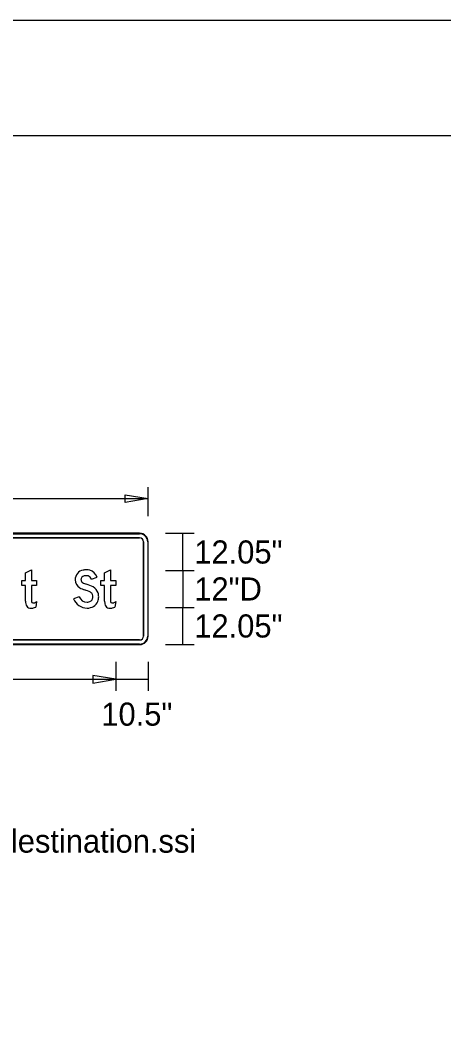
# Model space of a CAD drawing. Extents: x 1806251 to 1809821, y 414895 to 422886.
# Drawn here: x 1809677.959 to 1809679.337, y 415000.976 to 415004.226 of the extents above; entities that cross this region are included whole.
import ezdxf

# ---------------------------------------------------------------- set-up
doc = ezdxf.new("R2010")
doc.units = 0
for name, color, linetype in [('GSBWFILL', 7, 'Continuous'), ('GSCOLORFILL', 7, 'Continuous'), ('GSDIMS', 7, 'Continuous'), ('GSOUTLINE', 7, 'Continuous'), ('GSSHT', 7, 'Continuous')]:
    doc.layers.add(name, color=color, linetype=linetype)

msp = doc.modelspace()

# ---------------------------------------------------------------- linework, layer by layer
at = {"layer": 'GSBWFILL'}
for p, q in [((1809678.3481, 415002.5611), (1809676.8421, 415002.5611)), ((1809676.8421, 415002.5461), (1809678.3481, 415002.5461)), ((1809678.3606, 415002.5336), (1809678.3606, 415002.2276)), ((1809678.3756, 415002.2276), (1809678.3756, 415002.5336)), ((1809678.0134, 415002.3398), (1809678.0108, 415002.322)), ((1809678.2702, 415002.3398), (1809678.2676, 415002.322)), ((1809678.3481, 415002.2151), (1809676.8422, 415002.2151)), ((1809676.8422, 415002.2001), (1809678.3481, 415002.2001))]:
    msp.add_line(p, q, dxfattribs=at)
for points in [[(1809677.9774, 415002.341), (1809677.9774, 415002.3914), (1809677.9654, 415002.3914), (1809677.9654, 415002.4082), (1809677.9774, 415002.4082), (1809677.9774, 415002.4331), (1809677.9966, 415002.4427), (1809677.9966, 415002.4082), (1809678.0134, 415002.4082), (1809678.0134, 415002.3914), (1809677.9966, 415002.3914), (1809677.9966, 415002.344)], [(1809678.1916, 415002.4123), (1809678.2098, 415002.4184)], [(1809678.2342, 415002.341), (1809678.2342, 415002.3914), (1809678.2222, 415002.3914), (1809678.2222, 415002.4082), (1809678.2342, 415002.4082), (1809678.2342, 415002.4331), (1809678.2534, 415002.4427), (1809678.2534, 415002.4082), (1809678.2702, 415002.4082), (1809678.2702, 415002.3914), (1809678.2534, 415002.3914), (1809678.2534, 415002.344)], [(1809678.1514, 415002.3555), (1809678.1334, 415002.3487)]]:
    msp.add_lwpolyline(points, dxfattribs=at)
for centre, radius, start, end in [((1809678.3481, 415002.5336), 0.0275, 0, 90), ((1809678.3481, 415002.5336), 0.0125, 0, 90), ((1809678.3481, 415002.2276), 0.0275, 270, 0), ((1809678.3481, 415002.2276), 0.0125, 270, 0)]:
    msp.add_arc(centre, radius, start, end, dxfattribs=at)
for centre, major_axis, ratio, start_param, end_param in [((1809678.1703, 415002.4103), (0, 0.032), 0.999999, 0.175685, 1.570796), ((1809678.1703, 415002.4103), (0, 0.0128), 0.999999, 0.175685, 1.570796), ((1809678.1739, 415002.3905), (0, 0.0521), 0.999999, 0.090794, 0.175685), ((1809678.1739, 415002.3905), (0, 0.0329), 0.999999, 0.090794, 0.175685), ((1809678.1755, 415002.3729), (0, 0.0698), 0.999999, 6.283185, 6.373979), ((1809678.1755, 415002.3729), (0, 0.0506), 0.999999, 0, 0.090794), ((1809678.1755, 415002.4045), (0, 0.0382), 0.999999, 6.012094, 6.283185), ((1809678.1755, 415002.4045), (0, 0.019), 0.999999, 6.012094, 6.283185), ((1809678.1762, 415002.4072), (0, 0.0162), 0.999999, 5.034126, 6.012094), ((1809678.1762, 415002.4072), (0, 0.0354), 0.999999, 5.034126, 6.012094), ((1809678.168, 415002.4103), (0, 0.0296), 0.999999, 1.570796, 2.627164), ((1809678.168, 415002.4103), (0, 0.0104), 0.999999, 1.570796, 2.627164), ((1809678.1951, 415002.4583), (0, 0.0655), 0.999999, 2.627164, 2.834816), ((1809678.1303, 415002.2539), (0, 0.149), 0.999999, 5.820582, 5.976409), ((1809678.1825, 415002.3585), (0, 0.032), 0.999999, 5.010707, 5.820582), ((1809678.1771, 415002.3652), (0, 0.0275), 0.999999, 1.931277, 3.141593), ((1809678.1951, 415002.4583), (0, 0.0847), 0.999999, 2.627164, 2.834816), ((1809678.1303, 415002.2539), (0, 0.1298), 0.999999, 5.820582, 5.976409), ((1809678.1825, 415002.3585), (0, 0.0128), 0.999999, 5.010707, 5.820582), ((1809678.1753, 415002.3552), (0, 0.0205), 0.999999, 4.331279, 4.712389), ((1809678.1716, 415002.3552), (0, 0.0242), 0.999999, 4.712389, 5.010707), ((1809678.1753, 415002.3552), (0, 0.0397), 0.999999, 4.331279, 4.712389), ((1809678.1716, 415002.3552), (0, 0.0434), 0.999999, 4.712389, 5.010707), ((1809678.0284, 415002.341), (0, 0.051), 0.999998, 1.570796, 1.662322), ((1809678.0078, 415002.3389), (0, 0.0303), 0.999998, 1.653079, 1.937165), ((1809677.9948, 415002.3338), (0, 0.0164), 0.999998, 1.936133, 2.408497), ((1809677.9932, 415002.3327), (0, 0.0144), 0.999998, 2.436385, 2.996739), ((1809678.0296, 415002.344), (0, 0.033), 0.999998, 1.570796, 1.695783), ((1809678.0016, 415002.3405), (0, 0.0048), 0.999998, 1.695783, 2.93591), ((1809678.0031, 415002.3474), (0, 0.0119), 0.999998, 2.93591, 3.141593), ((1809678.0031, 415002.3527), (0, 0.0171), 0.999998, 3.141593, 3.322139), ((1809677.9889, 415002.3683), (0, 0.0512), 0.999998, 3.420942, 3.583276), ((1809678.0045, 415002.3447), (0, 0.009), 0.999998, 3.322139, 3.602705), ((1809677.9972, 415002.3594), (0, 0.0254), 0.999998, 3.602705, 3.831871), ((1809678.1771, 415002.3652), (0, 0.0467), 0.999999, 1.931277, 3.141593), ((1809678.1771, 415002.3602), (0, 0.0225), 0.999999, 3.141593, 3.672524), ((1809678.1771, 415002.3602), (0, 0.0417), 0.999999, 3.141593, 3.672524), ((1809678.1815, 415002.3527), (0, 0.0139), 0.999999, 3.672524, 4.331279), ((1809678.1815, 415002.3527), (0, 0.0331), 0.999999, 3.672524, 4.331279), ((1809678.2852, 415002.341), (0, 0.051), 0.999996, 1.570796, 1.662322), ((1809678.2646, 415002.3389), (0, 0.0303), 0.999996, 1.653079, 1.937165), ((1809678.2516, 415002.3338), (0, 0.0164), 0.999996, 1.936133, 2.408497), ((1809678.25, 415002.3327), (0, 0.0144), 0.999996, 2.436385, 2.996739), ((1809678.2864, 415002.344), (0, 0.033), 0.999996, 1.570796, 1.695783), ((1809678.2584, 415002.3405), (0, 0.0048), 0.999996, 1.695783, 2.93591), ((1809678.2599, 415002.3474), (0, 0.0119), 0.999996, 2.93591, 3.141593), ((1809678.2599, 415002.3527), (0, 0.0171), 0.999996, 3.141593, 3.322139), ((1809678.2457, 415002.3683), (0, 0.0512), 0.999996, 3.420942, 3.583276), ((1809678.2613, 415002.3447), (0, 0.009), 0.999996, 3.322139, 3.602705), ((1809678.254, 415002.3594), (0, 0.0254), 0.999996, 3.602705, 3.831871), ((1809677.996, 415002.3736), (0, 0.0554), 0.999998, 3.052778, 3.141593), ((1809677.996, 415002.3507), (0, 0.0325), 0.999998, 3.141593, 3.24959), ((1809677.9973, 415002.3392), (0, 0.021), 0.999998, 3.24959, 3.420941), ((1809678.2528, 415002.3736), (0, 0.0554), 0.999996, 3.052778, 3.141593), ((1809678.2528, 415002.3507), (0, 0.0325), 0.999996, 3.141593, 3.24959), ((1809678.2541, 415002.3392), (0, 0.021), 0.999996, 3.24959, 3.420941)]:
    msp.add_ellipse(centre, major_axis=major_axis, ratio=ratio, start_param=start_param, end_param=end_param, dxfattribs=at)
at = {"layer": 'GSCOLORFILL'}
for p, q in [((1809678.3481, 415002.5611), (1809676.8421, 415002.5611)), ((1809678.3481, 415002.5611), (1809676.8421, 415002.5611)), ((1809678.3481, 415002.5611), (1809676.8421, 415002.5611)), ((1809676.8421, 415002.5596), (1809678.3481, 415002.5596)), ((1809676.8421, 415002.5461), (1809678.3481, 415002.5461)), ((1809678.3606, 415002.5336), (1809678.3606, 415002.2276)), ((1809678.3741, 415002.5336), (1809678.3741, 415002.2276)), ((1809678.3756, 415002.2276), (1809678.3756, 415002.5336)), ((1809678.3756, 415002.2276), (1809678.3756, 415002.5336)), ((1809678.3756, 415002.2276), (1809678.3756, 415002.5336)), ((1809678.0134, 415002.3398), (1809678.0108, 415002.322)), ((1809678.2702, 415002.3398), (1809678.2676, 415002.322)), ((1809678.3481, 415002.2016), (1809676.8421, 415002.2016)), ((1809676.8421, 415002.2001), (1809678.3481, 415002.2001)), ((1809676.8421, 415002.2001), (1809678.3481, 415002.2001)), ((1809678.3481, 415002.2151), (1809676.8422, 415002.2151)), ((1809676.8422, 415002.2001), (1809678.3481, 415002.2001))]:
    msp.add_line(p, q, dxfattribs=at)
for points in [[(1809677.9774, 415002.341), (1809677.9774, 415002.3914), (1809677.9654, 415002.3914), (1809677.9654, 415002.4082), (1809677.9774, 415002.4082), (1809677.9774, 415002.4331), (1809677.9966, 415002.4427), (1809677.9966, 415002.4082), (1809678.0134, 415002.4082), (1809678.0134, 415002.3914), (1809677.9966, 415002.3914), (1809677.9966, 415002.344)], [(1809678.1916, 415002.4123), (1809678.2098, 415002.4184)], [(1809678.2342, 415002.341), (1809678.2342, 415002.3914), (1809678.2222, 415002.3914), (1809678.2222, 415002.4082), (1809678.2342, 415002.4082), (1809678.2342, 415002.4331), (1809678.2534, 415002.4427), (1809678.2534, 415002.4082), (1809678.2702, 415002.4082), (1809678.2702, 415002.3914), (1809678.2534, 415002.3914), (1809678.2534, 415002.344)], [(1809678.1514, 415002.3555), (1809678.1334, 415002.3487)]]:
    msp.add_lwpolyline(points, dxfattribs=at)
for centre, radius, start, end in [((1809678.3481, 415002.5336), 0.0275, 0, 90), ((1809678.3481, 415002.5336), 0.0275, 0, 90), ((1809678.3481, 415002.5336), 0.0275, 0, 90), ((1809678.3481, 415002.5336), 0.026, 0, 90), ((1809678.3481, 415002.5336), 0.0125, 0, 90), ((1809678.3481, 415002.2276), 0.0275, 270, 0), ((1809678.3481, 415002.2276), 0.0275, 270, 0), ((1809678.3481, 415002.2276), 0.0125, 270, 0), ((1809678.3481, 415002.2276), 0.0275, 270, 0), ((1809678.3481, 415002.2276), 0.026, 270, 0)]:
    msp.add_arc(centre, radius, start, end, dxfattribs=at)
for centre, major_axis, ratio, start_param, end_param in [((1809678.1703, 415002.4103), (0, 0.032), 0.999999, 0.175685, 1.570796), ((1809678.1703, 415002.4103), (0, 0.0128), 0.999999, 0.175685, 1.570796), ((1809678.1739, 415002.3905), (0, 0.0521), 0.999999, 0.090794, 0.175685), ((1809678.1739, 415002.3905), (0, 0.0329), 0.999999, 0.090794, 0.175685), ((1809678.1755, 415002.3729), (0, 0.0698), 0.999999, 6.283185, 6.373979), ((1809678.1755, 415002.3729), (0, 0.0506), 0.999999, 0, 0.090794), ((1809678.1755, 415002.4045), (0, 0.0382), 0.999999, 6.012094, 6.283185), ((1809678.1755, 415002.4045), (0, 0.019), 0.999999, 6.012094, 6.283185), ((1809678.1762, 415002.4072), (0, 0.0162), 0.999999, 5.034126, 6.012094), ((1809678.1762, 415002.4072), (0, 0.0354), 0.999999, 5.034126, 6.012094), ((1809678.168, 415002.4103), (0, 0.0296), 0.999999, 1.570796, 2.627164), ((1809678.168, 415002.4103), (0, 0.0104), 0.999999, 1.570796, 2.627164), ((1809678.1951, 415002.4583), (0, 0.0655), 0.999999, 2.627164, 2.834816), ((1809678.1303, 415002.2539), (0, 0.149), 0.999999, 5.820582, 5.976409), ((1809678.1825, 415002.3585), (0, 0.032), 0.999999, 5.010707, 5.820582), ((1809678.1771, 415002.3652), (0, 0.0275), 0.999999, 1.931277, 3.141593), ((1809678.1951, 415002.4583), (0, 0.0847), 0.999999, 2.627164, 2.834816), ((1809678.1303, 415002.2539), (0, 0.1298), 0.999999, 5.820582, 5.976409), ((1809678.1825, 415002.3585), (0, 0.0128), 0.999999, 5.010707, 5.820582), ((1809678.1753, 415002.3552), (0, 0.0205), 0.999999, 4.331279, 4.712389), ((1809678.1716, 415002.3552), (0, 0.0242), 0.999999, 4.712389, 5.010707), ((1809678.1753, 415002.3552), (0, 0.0397), 0.999999, 4.331279, 4.712389), ((1809678.1716, 415002.3552), (0, 0.0434), 0.999999, 4.712389, 5.010707), ((1809678.0284, 415002.341), (0, 0.051), 0.999998, 1.570796, 1.662322), ((1809678.0078, 415002.3389), (0, 0.0303), 0.999998, 1.653079, 1.937165), ((1809677.9948, 415002.3338), (0, 0.0164), 0.999998, 1.936133, 2.408497), ((1809677.9932, 415002.3327), (0, 0.0144), 0.999998, 2.436385, 2.996739), ((1809678.0296, 415002.344), (0, 0.033), 0.999998, 1.570796, 1.695783), ((1809678.0016, 415002.3405), (0, 0.0048), 0.999998, 1.695783, 2.93591), ((1809678.0031, 415002.3474), (0, 0.0119), 0.999998, 2.93591, 3.141593), ((1809678.0031, 415002.3527), (0, 0.0171), 0.999998, 3.141593, 3.322139), ((1809677.9889, 415002.3683), (0, 0.0512), 0.999998, 3.420942, 3.583276), ((1809678.0045, 415002.3447), (0, 0.009), 0.999998, 3.322139, 3.602705), ((1809677.9972, 415002.3594), (0, 0.0254), 0.999998, 3.602705, 3.831871), ((1809678.1771, 415002.3652), (0, 0.0467), 0.999999, 1.931277, 3.141593), ((1809678.1771, 415002.3602), (0, 0.0225), 0.999999, 3.141593, 3.672524), ((1809678.1771, 415002.3602), (0, 0.0417), 0.999999, 3.141593, 3.672524), ((1809678.1815, 415002.3527), (0, 0.0139), 0.999999, 3.672524, 4.331279), ((1809678.1815, 415002.3527), (0, 0.0331), 0.999999, 3.672524, 4.331279), ((1809678.2852, 415002.341), (0, 0.051), 0.999996, 1.570796, 1.662322), ((1809678.2646, 415002.3389), (0, 0.0303), 0.999996, 1.653079, 1.937165), ((1809678.2516, 415002.3338), (0, 0.0164), 0.999996, 1.936133, 2.408497), ((1809678.25, 415002.3327), (0, 0.0144), 0.999996, 2.436385, 2.996739), ((1809678.2864, 415002.344), (0, 0.033), 0.999996, 1.570796, 1.695783), ((1809678.2584, 415002.3405), (0, 0.0048), 0.999996, 1.695783, 2.93591), ((1809678.2599, 415002.3474), (0, 0.0119), 0.999996, 2.93591, 3.141593), ((1809678.2599, 415002.3527), (0, 0.0171), 0.999996, 3.141593, 3.322139), ((1809678.2457, 415002.3683), (0, 0.0512), 0.999996, 3.420942, 3.583276), ((1809678.2613, 415002.3447), (0, 0.009), 0.999996, 3.322139, 3.602705), ((1809678.254, 415002.3594), (0, 0.0254), 0.999996, 3.602705, 3.831871), ((1809677.996, 415002.3736), (0, 0.0554), 0.999998, 3.052778, 3.141593), ((1809677.996, 415002.3507), (0, 0.0325), 0.999998, 3.141593, 3.24959), ((1809677.9973, 415002.3392), (0, 0.021), 0.999998, 3.24959, 3.420941), ((1809678.2528, 415002.3736), (0, 0.0554), 0.999996, 3.052778, 3.141593), ((1809678.2528, 415002.3507), (0, 0.0325), 0.999996, 3.141593, 3.24959), ((1809678.2541, 415002.3392), (0, 0.021), 0.999996, 3.24959, 3.420941)]:
    msp.add_ellipse(centre, major_axis=major_axis, ratio=ratio, start_param=start_param, end_param=end_param, dxfattribs=at)
at = {"layer": 'GSDIMS'}
for p, q in [((1809678.3756, 415002.6173), (1809678.3756, 415002.7111)), ((1809676.8146, 415002.6736), (1809678.3756, 415002.6736)), ((1809678.4318, 415002.5611), (1809678.5256, 415002.5611)), ((1809678.4881, 415002.4406), (1809678.4881, 415002.5611)), ((1809678.4318, 415002.4406), (1809678.5256, 415002.4406)), ((1809678.4318, 415002.4406), (1809678.5256, 415002.4406)), ((1809678.4881, 415002.4406), (1809678.4881, 415002.3206)), ((1809678.4318, 415002.3206), (1809678.5256, 415002.3206)), ((1809678.4318, 415002.3206), (1809678.5256, 415002.3206)), ((1809678.4881, 415002.2001), (1809678.4881, 415002.3206)), ((1809678.4318, 415002.2001), (1809678.5256, 415002.2001)), ((1809678.2706, 415002.1438), (1809678.2706, 415002.0501)), ((1809678.2706, 415002.1438), (1809678.2706, 415002.0501)), ((1809678.3756, 415002.1438), (1809678.3756, 415002.0501)), ((1809676.9316, 415002.0876), (1809678.2706, 415002.0876)), ((1809678.2706, 415002.0876), (1809678.3756, 415002.0876))]:
    msp.add_line(p, q, dxfattribs=at)
for points in [[(1809678.3756, 415002.6736), (1809678.3006, 415002.6611), (1809678.3006, 415002.6861)], [(1809678.2706, 415002.0876), (1809678.1956, 415002.1001), (1809678.1956, 415002.0751)]]:
    msp.add_lwpolyline(points, close=True, dxfattribs=at)
at = {"layer": 'GSOUTLINE'}
for p, q in [((1809678.3481, 415002.5611), (1809676.8421, 415002.5611)), ((1809678.3481, 415002.5461), (1809676.8421, 415002.5461)), ((1809678.3606, 415002.2276), (1809678.3606, 415002.5336)), ((1809678.3756, 415002.2276), (1809678.3756, 415002.5336)), ((1809678.0134, 415002.3398), (1809678.0108, 415002.322)), ((1809678.2702, 415002.3398), (1809678.2676, 415002.322)), ((1809676.8421, 415002.2151), (1809678.3481, 415002.2151)), ((1809676.8421, 415002.2001), (1809678.3481, 415002.2001))]:
    msp.add_line(p, q, dxfattribs=at)
for points in [[(1809677.9774, 415002.341), (1809677.9774, 415002.3914), (1809677.9654, 415002.3914), (1809677.9654, 415002.4082), (1809677.9774, 415002.4082), (1809677.9774, 415002.4331), (1809677.9966, 415002.4427), (1809677.9966, 415002.4082), (1809678.0134, 415002.4082), (1809678.0134, 415002.3914), (1809677.9966, 415002.3914), (1809677.9966, 415002.344)], [(1809678.1916, 415002.4123), (1809678.2098, 415002.4184)], [(1809678.2342, 415002.341), (1809678.2342, 415002.3914), (1809678.2222, 415002.3914), (1809678.2222, 415002.4082), (1809678.2342, 415002.4082), (1809678.2342, 415002.4331), (1809678.2534, 415002.4427), (1809678.2534, 415002.4082), (1809678.2702, 415002.4082), (1809678.2702, 415002.3914), (1809678.2534, 415002.3914), (1809678.2534, 415002.344)], [(1809678.1514, 415002.3555), (1809678.1334, 415002.3487)]]:
    msp.add_lwpolyline(points, dxfattribs=at)
for centre, radius, start, end in [((1809678.3481, 415002.5336), 0.0275, 0, 90), ((1809678.3481, 415002.5336), 0.0125, 0, 90), ((1809678.3481, 415002.2276), 0.0275, 270, 0), ((1809678.3481, 415002.2276), 0.0125, 270, 0)]:
    msp.add_arc(centre, radius, start, end, dxfattribs=at)
for centre, major_axis, ratio, start_param, end_param in [((1809678.1703, 415002.4103), (0, 0.032), 0.999999, 0.175685, 1.570796), ((1809678.1703, 415002.4103), (0, 0.0128), 0.999999, 0.175685, 1.570796), ((1809678.1739, 415002.3905), (0, 0.0521), 0.999999, 0.090794, 0.175685), ((1809678.1739, 415002.3905), (0, 0.0329), 0.999999, 0.090794, 0.175685), ((1809678.1755, 415002.3729), (0, 0.0698), 0.999999, 6.283185, 6.373979), ((1809678.1755, 415002.3729), (0, 0.0506), 0.999999, 0, 0.090794), ((1809678.1755, 415002.4045), (0, 0.0382), 0.999999, 6.012094, 6.283185), ((1809678.1755, 415002.4045), (0, 0.019), 0.999999, 6.012094, 6.283185), ((1809678.1762, 415002.4072), (0, 0.0162), 0.999999, 5.034126, 6.012094), ((1809678.1762, 415002.4072), (0, 0.0354), 0.999999, 5.034126, 6.012094), ((1809678.168, 415002.4103), (0, 0.0296), 0.999999, 1.570796, 2.627164), ((1809678.168, 415002.4103), (0, 0.0104), 0.999999, 1.570796, 2.627164), ((1809678.1951, 415002.4583), (0, 0.0655), 0.999999, 2.627164, 2.834816), ((1809678.1303, 415002.2539), (0, 0.149), 0.999999, 5.820582, 5.976409), ((1809678.1825, 415002.3585), (0, 0.032), 0.999999, 5.010707, 5.820582), ((1809678.1771, 415002.3652), (0, 0.0275), 0.999999, 1.931277, 3.141593), ((1809678.1951, 415002.4583), (0, 0.0847), 0.999999, 2.627164, 2.834816), ((1809678.1303, 415002.2539), (0, 0.1298), 0.999999, 5.820582, 5.976409), ((1809678.1825, 415002.3585), (0, 0.0128), 0.999999, 5.010707, 5.820582), ((1809678.1753, 415002.3552), (0, 0.0205), 0.999999, 4.331279, 4.712389), ((1809678.1716, 415002.3552), (0, 0.0242), 0.999999, 4.712389, 5.010707), ((1809678.1753, 415002.3552), (0, 0.0397), 0.999999, 4.331279, 4.712389), ((1809678.1716, 415002.3552), (0, 0.0434), 0.999999, 4.712389, 5.010707), ((1809678.0284, 415002.341), (0, 0.051), 0.999998, 1.570796, 1.662322), ((1809678.0078, 415002.3389), (0, 0.0303), 0.999998, 1.653079, 1.937165), ((1809677.9948, 415002.3338), (0, 0.0164), 0.999998, 1.936133, 2.408497), ((1809677.9932, 415002.3327), (0, 0.0144), 0.999998, 2.436385, 2.996739), ((1809678.0296, 415002.344), (0, 0.033), 0.999998, 1.570796, 1.695783), ((1809678.0016, 415002.3405), (0, 0.0048), 0.999998, 1.695783, 2.93591), ((1809678.0031, 415002.3474), (0, 0.0119), 0.999998, 2.93591, 3.141593), ((1809678.0031, 415002.3527), (0, 0.0171), 0.999998, 3.141593, 3.322139), ((1809677.9889, 415002.3683), (0, 0.0512), 0.999998, 3.420942, 3.583276), ((1809678.0045, 415002.3447), (0, 0.009), 0.999998, 3.322139, 3.602705), ((1809677.9972, 415002.3594), (0, 0.0254), 0.999998, 3.602705, 3.831871), ((1809678.1771, 415002.3652), (0, 0.0467), 0.999999, 1.931277, 3.141593), ((1809678.1771, 415002.3602), (0, 0.0225), 0.999999, 3.141593, 3.672524), ((1809678.1771, 415002.3602), (0, 0.0417), 0.999999, 3.141593, 3.672524), ((1809678.1815, 415002.3527), (0, 0.0139), 0.999999, 3.672524, 4.331279), ((1809678.1815, 415002.3527), (0, 0.0331), 0.999999, 3.672524, 4.331279), ((1809678.2852, 415002.341), (0, 0.051), 0.999996, 1.570796, 1.662322), ((1809678.2646, 415002.3389), (0, 0.0303), 0.999996, 1.653079, 1.937165), ((1809678.2516, 415002.3338), (0, 0.0164), 0.999996, 1.936133, 2.408497), ((1809678.25, 415002.3327), (0, 0.0144), 0.999996, 2.436385, 2.996739), ((1809678.2864, 415002.344), (0, 0.033), 0.999996, 1.570796, 1.695783), ((1809678.2584, 415002.3405), (0, 0.0048), 0.999996, 1.695783, 2.93591), ((1809678.2599, 415002.3474), (0, 0.0119), 0.999996, 2.93591, 3.141593), ((1809678.2599, 415002.3527), (0, 0.0171), 0.999996, 3.141593, 3.322139), ((1809678.2457, 415002.3683), (0, 0.0512), 0.999996, 3.420942, 3.583276), ((1809678.2613, 415002.3447), (0, 0.009), 0.999996, 3.322139, 3.602705), ((1809678.254, 415002.3594), (0, 0.0254), 0.999996, 3.602705, 3.831871), ((1809677.996, 415002.3736), (0, 0.0554), 0.999998, 3.052778, 3.141593), ((1809677.996, 415002.3507), (0, 0.0325), 0.999998, 3.141593, 3.24959), ((1809677.9973, 415002.3392), (0, 0.021), 0.999998, 3.24959, 3.420941), ((1809678.2528, 415002.3736), (0, 0.0554), 0.999996, 3.052778, 3.141593), ((1809678.2528, 415002.3507), (0, 0.0325), 0.999996, 3.141593, 3.24959), ((1809678.2541, 415002.3392), (0, 0.021), 0.999996, 3.24959, 3.420941)]:
    msp.add_ellipse(centre, major_axis=major_axis, ratio=ratio, start_param=start_param, end_param=end_param, dxfattribs=at)
at = {"layer": 'GSSHT'}
msp.add_line((1809672.1349, 415004.2262), (1809684.8891, 415004.2262), dxfattribs=at)
msp.add_lwpolyline([(1809672.634, 415003.8512), (1809684.6381, 415003.8512), (1809684.6381, 414996.3475), (1809672.634, 414996.3475)], close=True, dxfattribs=at)

# ---------------------------------------------------------------- texts
at = {"layer": 'GSDIMS'}
for s, p in [('12.05"', (1809678.5256, 415002.4631)), ('12"D', (1809678.5256, 415002.3431)), ('12.05"', (1809678.5256, 415002.2231)), ('10.5"', (1809678.2236, 415001.9371)), ('Panel Style: guide_con_destination.ssi', (1809676.8146, 415001.5251))]:
    msp.add_text(s, height=0.075, dxfattribs=at).set_placement(p)

doc.saveas('drawing.dxf')
